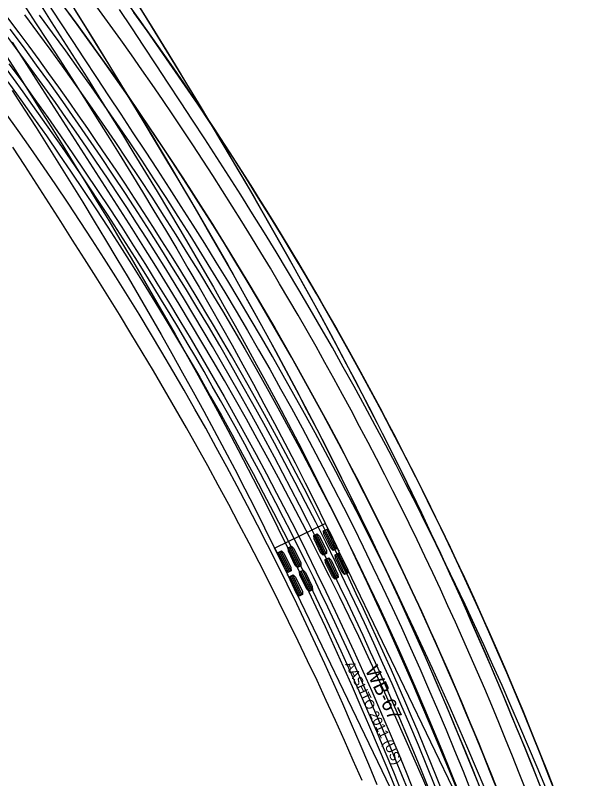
# Model space of a CAD drawing. Extents: x 916040 to 917457, y 328936 to 330267.
# Drawn here: x 916742.6 to 916826.9, y 329306.5 to 329421.5 of the extents above; entities that cross this region are included whole.
import ezdxf

# ---------------------------------------------------------------- set-up
doc = ezdxf.new("R2010")
doc.units = 0
for name, color, linetype in [('EB_RightontoSaco_WB67_v2', 7, 'Continuous'), ('NB_LeftontoRoute25_WB67', 7, 'Continuous'), ('NB_RightontoRoute25_WB67', 7, 'Continuous'), ('NB_ThruontoManchester_WB67', 7, 'Continuous'), ('SB_LeftontoRoute25_WB67', 7, 'Continuous'), ('SB_ThruontonSacoRd_WB67', 7, 'Continuous'), ('WB_LeftontoSaco_WB67', 7, 'Continuous')]:
    doc.layers.add(name, color=color, linetype=linetype)

msp = doc.modelspace()

# ---------------------------------------------------------------- linework, layer by layer
at = {"layer": 'EB_RightontoSaco_WB67_v2'}
for points in [[(916746.23, 329423.34), (916748.03, 329420.53), (916749.83, 329417.72), (916751.62, 329414.9), (916753.41, 329412.08), (916755.19, 329409.25), (916756.96, 329406.41), (916758.72, 329403.57), (916760.47, 329400.72), (916762.21, 329397.87), (916763.94, 329395), (916765.66, 329392.14), (916767.37, 329389.26), (916769.06, 329386.37), (916770.74, 329383.48), (916772.41, 329380.58), (916774.06, 329377.67), (916775.7, 329374.76), (916777.32, 329371.83), (916778.93, 329368.9), (916780.53, 329365.96), (916782.1, 329363.01), (916783.67, 329360.05), (916785.21, 329357.08), (916786.74, 329354.1), (916788.25, 329351.12), (916789.75, 329348.12), (916791.22, 329345.12), (916792.68, 329342.11), (916794.12, 329339.09), (916795.55, 329336.05), (916796.96, 329333.01), (916798.35, 329329.96), (916799.72, 329326.9), (916801.08, 329323.84), (916802.42, 329320.77), (916803.75, 329317.69), (916805.06, 329314.6), (916806.35, 329311.51), (916807.63, 329308.41), (916808.9, 329305.31)], [(916746.2, 329421.54), (916748.18, 329418.86), (916750.14, 329416.17), (916752.09, 329413.46), (916754.02, 329410.73), (916755.94, 329407.99), (916757.83, 329405.23), (916759.72, 329402.46), (916761.58, 329399.68), (916763.43, 329396.88), (916765.25, 329394.07), (916767.07, 329391.24), (916768.86, 329388.41), (916770.63, 329385.56), (916772.39, 329382.7), (916774.13, 329379.82), (916775.85, 329376.94), (916777.54, 329374.04), (916779.23, 329371.13), (916780.89, 329368.21), (916782.53, 329365.28), (916784.15, 329362.34), (916785.76, 329359.39), (916787.34, 329356.43), (916788.91, 329353.45), (916790.45, 329350.47), (916791.98, 329347.47), (916793.48, 329344.47), (916794.97, 329341.46), (916796.43, 329338.43), (916797.88, 329335.4), (916799.31, 329332.35), (916800.71, 329329.3), (916802.1, 329326.24), (916803.46, 329323.17), (916804.81, 329320.09), (916806.13, 329317), (916807.44, 329313.9), (916808.72, 329310.8), (916809.98, 329307.68), (916811.23, 329304.56)], [(916740.88, 329415.95), (916742.67, 329413.15), (916744.45, 329410.35), (916746.22, 329407.54), (916747.99, 329404.73), (916749.74, 329401.92), (916751.49, 329399.1), (916753.22, 329396.28), (916754.95, 329393.45), (916756.66, 329390.62), (916758.36, 329387.78), (916760.05, 329384.94), (916761.72, 329382.09), (916763.38, 329379.23), (916765.03, 329376.36), (916766.66, 329373.49), (916768.28, 329370.61), (916769.88, 329367.72), (916771.47, 329364.83), (916773.04, 329361.93), (916774.6, 329359.02), (916776.14, 329356.1), (916777.66, 329353.17), (916779.17, 329350.24), (916780.66, 329347.3), (916782.13, 329344.35), (916783.59, 329341.39), (916785.02, 329338.42), (916786.44, 329335.44), (916787.85, 329332.46), (916789.24, 329329.46), (916790.61, 329326.45), (916791.96, 329323.44), (916793.3, 329320.42), (916794.62, 329317.38), (916795.93, 329314.34), (916797.22, 329311.3), (916798.51, 329308.24), (916799.77, 329305.18)], [(916741.66, 329414.23), (916743.62, 329411.53), (916745.57, 329408.83), (916747.49, 329406.11), (916749.39, 329403.38), (916751.28, 329400.65), (916753.14, 329397.9), (916754.99, 329395.14), (916756.82, 329392.37), (916758.62, 329389.6), (916760.41, 329386.8), (916762.18, 329384), (916763.93, 329381.19), (916765.66, 329378.37), (916767.38, 329375.53), (916769.07, 329372.69), (916770.74, 329369.83), (916772.4, 329366.97), (916774.03, 329364.09), (916775.65, 329361.2), (916777.25, 329358.3), (916778.83, 329355.39), (916780.39, 329352.48), (916781.93, 329349.55), (916783.45, 329346.61), (916784.95, 329343.66), (916786.43, 329340.7), (916787.89, 329337.73), (916789.33, 329334.75), (916790.75, 329331.77), (916792.16, 329328.77), (916793.54, 329325.77), (916794.9, 329322.75), (916796.24, 329319.73), (916797.57, 329316.69), (916798.87, 329313.65), (916800.15, 329310.6), (916801.41, 329307.55), (916802.65, 329304.48)]]:
    msp.add_lwpolyline(points, dxfattribs=at)
msp.add_arc((916337.91, 329118.02), 504.75, 18.7715, 37.1675, dxfattribs=at)
at = {"layer": 'NB_LeftontoRoute25_WB67'}
for points in [[(916760.52, 329424.03), (916762.27, 329421.19), (916764.02, 329418.34), (916765.77, 329415.49), (916767.51, 329412.63), (916769.24, 329409.77), (916770.97, 329406.9), (916772.69, 329404.03), (916774.39, 329401.15), (916776.09, 329398.26), (916777.78, 329395.37), (916779.46, 329392.47), (916781.13, 329389.57), (916782.78, 329386.65), (916784.42, 329383.73), (916786.05, 329380.81), (916787.66, 329377.87), (916789.27, 329374.93), (916790.85, 329371.98), (916792.42, 329369.02), (916793.98, 329366.05), (916795.52, 329363.08), (916797.05, 329360.09), (916798.56, 329357.1), (916800.05, 329354.1), (916801.53, 329351.1), (916802.99, 329348.08), (916804.43, 329345.06), (916805.86, 329342.03), (916807.26, 329338.99), (916808.65, 329335.95), (916810.03, 329332.9), (916811.38, 329329.84), (916812.72, 329326.77), (916814.05, 329323.7), (916815.36, 329320.62), (916816.66, 329317.53), (916817.94, 329314.44), (916819.21, 329311.35), (916820.47, 329308.25), (916821.71, 329305.15)], [(916749.78, 329423.01), (916751.76, 329420.32), (916753.72, 329417.62), (916755.65, 329414.92), (916757.57, 329412.2), (916759.48, 329409.47), (916761.36, 329406.72), (916763.22, 329403.97), (916765.06, 329401.21), (916766.89, 329398.44), (916768.7, 329395.65), (916770.49, 329392.86), (916772.26, 329390.05), (916774.01, 329387.24), (916775.74, 329384.41), (916777.46, 329381.57), (916779.15, 329378.72), (916780.83, 329375.86), (916782.49, 329372.99), (916784.13, 329370.11), (916785.75, 329367.22), (916787.35, 329364.32), (916788.93, 329361.41), (916790.5, 329358.49), (916792.04, 329355.55), (916793.57, 329352.61), (916795.08, 329349.66), (916796.57, 329346.7), (916798.04, 329343.73), (916799.48, 329340.75), (916800.92, 329337.76), (916802.33, 329334.76), (916803.72, 329331.76), (916805.09, 329328.74), (916806.44, 329325.71), (916807.78, 329322.68), (916809.09, 329319.64), (916810.38, 329316.59), (916811.66, 329313.53), (916812.91, 329310.46), (916814.15, 329307.39), (916815.36, 329304.3)], [(916751.53, 329422.4), (916753.29, 329419.57), (916755.03, 329416.73), (916756.78, 329413.89), (916758.51, 329411.06), (916760.24, 329408.21), (916761.97, 329405.37), (916763.68, 329402.52), (916765.38, 329399.67), (916767.08, 329396.82), (916768.76, 329393.96), (916770.43, 329391.1), (916772.1, 329388.23), (916773.74, 329385.35), (916775.38, 329382.47), (916777, 329379.58), (916778.61, 329376.69), (916780.21, 329373.79), (916781.79, 329370.88), (916783.36, 329367.97), (916784.91, 329365.05), (916786.45, 329362.12), (916787.97, 329359.18), (916789.47, 329356.24), (916790.96, 329353.29), (916792.43, 329350.33), (916793.89, 329347.37), (916795.33, 329344.4), (916796.75, 329341.41), (916798.16, 329338.43), (916799.54, 329335.44), (916800.91, 329332.44), (916802.27, 329329.43), (916803.61, 329326.41), (916804.93, 329323.38), (916806.24, 329320.35), (916807.53, 329317.31), (916808.81, 329314.26), (916810.08, 329311.2), (916811.34, 329308.14), (916812.58, 329305.07)], [(916760.21, 329422.3), (916762.15, 329419.58), (916764.09, 329416.84), (916766, 329414.09), (916767.9, 329411.33), (916769.78, 329408.55), (916771.65, 329405.76), (916773.49, 329402.95), (916775.32, 329400.13), (916777.14, 329397.3), (916778.93, 329394.46), (916780.71, 329391.61), (916782.47, 329388.74), (916784.21, 329385.86), (916785.93, 329382.97), (916787.63, 329380.07), (916789.31, 329377.16), (916790.98, 329374.24), (916792.63, 329371.31), (916794.25, 329368.36), (916795.86, 329365.41), (916797.45, 329362.44), (916799.02, 329359.46), (916800.57, 329356.48), (916802.1, 329353.48), (916803.62, 329350.48), (916805.11, 329347.46), (916806.58, 329344.44), (916808.04, 329341.4), (916809.47, 329338.36), (916810.89, 329335.3), (916812.28, 329332.24), (916813.66, 329329.17), (916815.01, 329326.09), (916816.35, 329323), (916817.66, 329319.9), (916818.96, 329316.8), (916820.23, 329313.68), (916821.49, 329310.56), (916822.72, 329307.43), (916823.94, 329304.29)]]:
    msp.add_lwpolyline(points, dxfattribs=at)
msp.add_arc((916337.91, 329118.02), 516.5, 18.7715, 38.2197, dxfattribs=at)
at = {"layer": 'NB_RightontoRoute25_WB67'}
for points in [[(916813.31, 329304.99), (916812.03, 329308.03), (916810.73, 329311.08), (916809.41, 329314.11), (916808.08, 329317.14), (916806.74, 329320.15), (916805.37, 329323.17), (916803.99, 329326.17), (916802.6, 329329.16), (916801.19, 329332.15), (916799.76, 329335.13), (916798.31, 329338.1), (916796.85, 329341.06), (916795.37, 329344.01), (916793.88, 329346.95), (916792.36, 329349.89), (916790.83, 329352.81), (916789.29, 329355.73), (916787.72, 329358.63), (916786.14, 329361.53), (916784.54, 329364.41), (916782.92, 329367.29), (916781.29, 329370.15), (916779.64, 329373.01), (916777.97, 329375.85), (916776.28, 329378.69), (916774.57, 329381.51), (916772.85, 329384.32), (916771.11, 329387.13), (916769.36, 329389.92), (916767.58, 329392.71), (916765.79, 329395.5), (916763.99, 329398.28), (916762.18, 329401.06), (916760.36, 329403.84), (916758.53, 329406.61), (916756.7, 329409.39), (916754.86, 329412.17), (916753.03, 329414.95), (916751.2, 329417.73), (916749.37, 329420.52), (916747.55, 329423.32)], [(916815.41, 329304.18), (916814.19, 329307.27), (916812.96, 329310.35), (916811.7, 329313.42), (916810.43, 329316.48), (916809.13, 329319.53), (916807.82, 329322.58), (916806.49, 329325.62), (916805.13, 329328.64), (916803.76, 329331.66), (916802.37, 329334.67), (916800.96, 329337.67), (916799.53, 329340.66), (916798.08, 329343.64), (916796.61, 329346.61), (916795.12, 329349.57), (916793.62, 329352.52), (916792.09, 329355.46), (916790.55, 329358.4), (916788.98, 329361.32), (916787.4, 329364.23), (916785.8, 329367.13), (916784.18, 329370.02), (916782.54, 329372.9), (916780.88, 329375.77), (916779.21, 329378.63), (916777.51, 329381.48), (916775.8, 329384.31), (916774.07, 329387.14), (916772.32, 329389.95), (916770.55, 329392.76), (916768.77, 329395.55), (916766.96, 329398.33), (916765.14, 329401.1), (916763.3, 329403.85), (916761.45, 329406.6), (916759.57, 329409.33), (916757.68, 329412.05), (916755.77, 329414.76), (916753.84, 329417.45), (916751.9, 329420.13), (916749.94, 329422.81)], [(916822.44, 329305.17), (916821.15, 329308.27), (916819.85, 329311.35), (916818.54, 329314.43), (916817.2, 329317.51), (916815.85, 329320.58), (916814.49, 329323.64), (916813.11, 329326.69), (916811.71, 329329.73), (916810.3, 329332.77), (916808.86, 329335.8), (916807.41, 329338.82), (916805.95, 329341.84), (916804.46, 329344.84), (916802.96, 329347.84), (916801.44, 329350.82), (916799.91, 329353.8), (916798.35, 329356.77), (916796.78, 329359.73), (916795.19, 329362.68), (916793.59, 329365.62), (916791.96, 329368.55), (916790.32, 329371.47), (916788.66, 329374.39), (916786.98, 329377.29), (916785.28, 329380.18), (916783.57, 329383.06), (916781.84, 329385.92), (916780.09, 329388.78), (916778.32, 329391.63), (916776.54, 329394.46), (916774.75, 329397.29), (916772.94, 329400.1), (916771.12, 329402.91), (916769.29, 329405.71), (916767.46, 329408.5), (916765.63, 329411.29), (916763.79, 329414.07), (916761.96, 329416.85), (916760.13, 329419.63), (916758.3, 329422.4)], [(916824.13, 329303.8), (916822.92, 329306.93), (916821.69, 329310.06), (916820.44, 329313.18), (916819.17, 329316.29), (916817.88, 329319.39), (916816.57, 329322.49), (916815.24, 329325.58), (916813.88, 329328.66), (916812.51, 329331.73), (916811.12, 329334.79), (916809.71, 329337.85), (916808.28, 329340.89), (916806.83, 329343.93), (916805.36, 329346.95), (916803.87, 329349.97), (916802.36, 329352.98), (916800.83, 329355.97), (916799.28, 329358.96), (916797.72, 329361.94), (916796.13, 329364.91), (916794.52, 329367.86), (916792.9, 329370.81), (916791.26, 329373.75), (916789.59, 329376.67), (916787.91, 329379.59), (916786.21, 329382.49), (916784.49, 329385.38), (916782.75, 329388.27), (916781, 329391.14), (916779.22, 329394), (916777.43, 329396.84), (916775.62, 329399.68), (916773.79, 329402.5), (916771.94, 329405.32), (916770.07, 329408.12), (916768.19, 329410.9), (916766.28, 329413.68), (916764.36, 329416.44), (916762.43, 329419.19), (916760.47, 329421.93)]]:
    msp.add_lwpolyline(points, dxfattribs=at)
msp.add_arc((916337.91, 329118.02), 516.5, 18.7715, 38.2197, dxfattribs=at)
at = {"layer": 'NB_ThruontoManchester_WB67'}
for points in [[(916750.67, 329423.83), (916752.43, 329420.99), (916754.18, 329418.16), (916755.92, 329415.32), (916757.66, 329412.48), (916759.39, 329409.64), (916761.12, 329406.8), (916762.83, 329403.96), (916764.54, 329401.11), (916766.24, 329398.25), (916767.93, 329395.4), (916769.61, 329392.53), (916771.27, 329389.67), (916772.93, 329386.79), (916774.57, 329383.92), (916776.2, 329381.03), (916777.82, 329378.14), (916779.42, 329375.24), (916781.01, 329372.34), (916782.58, 329369.43), (916784.14, 329366.51), (916785.68, 329363.59), (916787.21, 329360.66), (916788.73, 329357.72), (916790.22, 329354.77), (916791.7, 329351.82), (916793.17, 329348.85), (916794.62, 329345.88), (916796.05, 329342.91), (916797.46, 329339.93), (916798.85, 329336.94), (916800.23, 329333.94), (916801.59, 329330.94), (916802.94, 329327.92), (916804.27, 329324.9), (916805.59, 329321.87), (916806.89, 329318.83), (916808.18, 329315.78), (916809.45, 329312.73), (916810.71, 329309.67), (916811.96, 329306.6), (916813.2, 329303.53)], [(916759.23, 329423.66), (916761.18, 329420.94), (916763.12, 329418.21), (916765.05, 329415.47), (916766.95, 329412.71), (916768.84, 329409.94), (916770.72, 329407.15), (916772.57, 329404.36), (916774.41, 329401.54), (916776.23, 329398.72), (916778.04, 329395.88), (916779.82, 329393.04), (916781.59, 329390.18), (916783.34, 329387.3), (916785.07, 329384.42), (916786.78, 329381.53), (916788.47, 329378.62), (916790.15, 329375.7), (916791.8, 329372.77), (916793.44, 329369.83), (916795.06, 329366.88), (916796.66, 329363.92), (916798.24, 329360.95), (916799.8, 329357.97), (916801.34, 329354.98), (916802.86, 329351.98), (916804.37, 329348.97), (916805.85, 329345.95), (916807.31, 329342.92), (916808.76, 329339.88), (916810.18, 329336.83), (916811.59, 329333.77), (916812.97, 329330.71), (916814.34, 329327.63), (916815.68, 329324.55), (916817.01, 329321.45), (916818.31, 329318.35), (916819.6, 329315.24), (916820.86, 329312.12), (916822.11, 329309), (916823.33, 329305.86)], [(916750.77, 329421.67), (916752.74, 329418.98), (916754.69, 329416.27), (916756.62, 329413.56), (916758.53, 329410.83), (916760.42, 329408.1), (916762.29, 329405.35), (916764.14, 329402.59), (916765.98, 329399.83), (916767.8, 329397.05), (916769.59, 329394.26), (916771.37, 329391.46), (916773.13, 329388.65), (916774.88, 329385.82), (916776.6, 329382.99), (916778.31, 329380.15), (916779.99, 329377.29), (916781.66, 329374.43), (916783.31, 329371.55), (916784.94, 329368.67), (916786.55, 329365.77), (916788.14, 329362.86), (916789.72, 329359.95), (916791.27, 329357.02), (916792.81, 329354.08), (916794.33, 329351.14), (916795.82, 329348.18), (916797.3, 329345.22), (916798.76, 329342.24), (916800.2, 329339.26), (916801.62, 329336.26), (916803.02, 329333.26), (916804.41, 329330.25), (916805.77, 329327.23), (916807.11, 329324.2), (916808.44, 329321.16), (916809.74, 329318.11), (916811.02, 329315.06), (916812.29, 329312), (916813.53, 329308.93), (916814.76, 329305.85)], [(916761.41, 329422.62), (916763.16, 329419.77), (916764.91, 329416.92), (916766.65, 329414.06), (916768.39, 329411.2), (916770.12, 329408.34), (916771.84, 329405.47), (916773.55, 329402.59), (916775.25, 329399.71), (916776.95, 329396.82), (916778.63, 329393.93), (916780.3, 329391.02), (916781.96, 329388.11), (916783.61, 329385.2), (916785.24, 329382.27), (916786.86, 329379.34), (916788.47, 329376.4), (916790.07, 329373.46), (916791.64, 329370.5), (916793.21, 329367.54), (916794.76, 329364.57), (916796.29, 329361.59), (916797.81, 329358.6), (916799.31, 329355.61), (916800.8, 329352.6), (916802.27, 329349.59), (916803.72, 329346.57), (916805.15, 329343.54), (916806.57, 329340.51), (916807.96, 329337.47), (916809.34, 329334.42), (916810.71, 329331.37), (916812.06, 329328.31), (916813.39, 329325.24), (916814.71, 329322.16), (916816.01, 329319.08), (916817.3, 329315.99), (916818.58, 329312.9), (916819.84, 329309.8), (916821.09, 329306.7), (916822.33, 329303.59)]]:
    msp.add_lwpolyline(points, dxfattribs=at)
msp.add_arc((916337.91, 329118.02), 516.5, 18.7715, 38.2197, dxfattribs=at)
at = {"layer": 'SB_LeftontoRoute25_WB67'}
msp.add_arc((916337.91, 329118.02), 500, 18.7715, 37.1675, dxfattribs=at)
at = {"layer": 'SB_ThruontonSacoRd_WB67'}
for points in [[(916805.8, 329305.36), (916804.54, 329308.47), (916803.26, 329311.58), (916801.96, 329314.68), (916800.64, 329317.77), (916799.3, 329320.85), (916797.93, 329323.92), (916796.55, 329326.99), (916795.14, 329330.04), (916793.72, 329333.09), (916792.27, 329336.12), (916790.81, 329339.15), (916789.32, 329342.17), (916787.82, 329345.18), (916786.29, 329348.17), (916784.74, 329351.16), (916783.18, 329354.14), (916781.59, 329357.1), (916779.99, 329360.06), (916778.36, 329363.01), (916776.72, 329365.94), (916775.05, 329368.86), (916773.37, 329371.78), (916771.66, 329374.68), (916769.94, 329377.57), (916768.2, 329380.44), (916766.44, 329383.31), (916764.66, 329386.17), (916762.86, 329389.01), (916761.04, 329391.84), (916759.2, 329394.66), (916757.35, 329397.46), (916755.47, 329400.26), (916753.58, 329403.04), (916751.67, 329405.8), (916749.74, 329408.56), (916747.79, 329411.3), (916745.82, 329414.03), (916743.84, 329416.75), (916741.83, 329419.45)], [(916805.23, 329303.51), (916803.92, 329306.59), (916802.59, 329309.66), (916801.25, 329312.73), (916799.89, 329315.79), (916798.51, 329318.84), (916797.12, 329321.89), (916795.71, 329324.92), (916794.28, 329327.95), (916792.83, 329330.98), (916791.37, 329333.99), (916789.89, 329336.99), (916788.39, 329339.99), (916786.87, 329342.97), (916785.34, 329345.95), (916783.79, 329348.92), (916782.21, 329351.87), (916780.63, 329354.82), (916779.02, 329357.76), (916777.39, 329360.69), (916775.75, 329363.61), (916774.08, 329366.51), (916772.4, 329369.41), (916770.7, 329372.3), (916768.99, 329375.17), (916767.25, 329378.04), (916765.51, 329380.9), (916763.74, 329383.75), (916761.97, 329386.58), (916760.19, 329389.42), (916758.4, 329392.24), (916756.6, 329395.06), (916754.8, 329397.87), (916752.99, 329400.68), (916751.18, 329403.48), (916749.38, 329406.28), (916747.57, 329409.08), (916745.77, 329411.88), (916743.97, 329414.68), (916742.18, 329417.48)], [(916797.07, 329305.62), (916795.8, 329308.69), (916794.52, 329311.74), (916793.21, 329314.79), (916791.89, 329317.83), (916790.54, 329320.85), (916789.18, 329323.87), (916787.8, 329326.88), (916786.39, 329329.88), (916784.97, 329332.87), (916783.52, 329335.85), (916782.06, 329338.82), (916780.57, 329341.78), (916779.07, 329344.73), (916777.55, 329347.67), (916776, 329350.6), (916774.44, 329353.52), (916772.86, 329356.43), (916771.26, 329359.33), (916769.64, 329362.22), (916768, 329365.09), (916766.34, 329367.96), (916764.66, 329370.81), (916762.96, 329373.65), (916761.25, 329376.49), (916759.51, 329379.31), (916757.76, 329382.11), (916755.99, 329384.91), (916754.2, 329387.7), (916752.39, 329390.47), (916750.56, 329393.23), (916748.71, 329395.98), (916746.85, 329398.71), (916744.97, 329401.44), (916743.06, 329404.15), (916741.15, 329406.85)], [(916794.8, 329306.27), (916793.47, 329309.3), (916792.13, 329312.32), (916790.77, 329315.33), (916789.4, 329318.33), (916788.01, 329321.32), (916786.6, 329324.31), (916785.18, 329327.29), (916783.73, 329330.25), (916782.28, 329333.21), (916780.8, 329336.16), (916779.31, 329339.1), (916777.8, 329342.03), (916776.27, 329344.95), (916774.72, 329347.87), (916773.15, 329350.77), (916771.57, 329353.66), (916769.97, 329356.54), (916768.35, 329359.41), (916766.72, 329362.27), (916765.06, 329365.12), (916763.39, 329367.96), (916761.7, 329370.8), (916759.99, 329373.62), (916758.27, 329376.44), (916756.53, 329379.26), (916754.77, 329382.07), (916753, 329384.87), (916751.22, 329387.68), (916749.44, 329390.48), (916747.64, 329393.28), (916745.84, 329396.08), (916744.04, 329398.88), (916742.23, 329401.68)]]:
    msp.add_lwpolyline(points, dxfattribs=at)
msp.add_arc((916337.91, 329118.02), 500, 18.7715, 37.1675, dxfattribs=at)
at = {"layer": 'WB_LeftontoSaco_WB67'}
for p, q in [((916789.3, 329344.98), (916781.65, 329341.29)), ((916812.3, 329297.22), (916789.3, 329344.98)), ((916790.49, 329340.94), (916789.05, 329343.91)), ((916790.69, 329341.04), (916789.26, 329344.01)), ((916790.9, 329341.14), (916789.47, 329344.11)), ((916789, 329340.22), (916787.57, 329343.2)), ((916789.21, 329340.32), (916787.77, 329343.3)), ((916789.41, 329340.42), (916787.98, 329343.39)), ((916781.65, 329341.29), (916804.64, 329293.54)), ((916785.14, 329338.36), (916783.71, 329341.34)), ((916785.35, 329338.46), (916783.91, 329341.44)), ((916785.55, 329338.56), (916784.12, 329341.54)), ((916783.65, 329337.65), (916782.22, 329340.62)), ((916783.86, 329337.75), (916782.43, 329340.72)), ((916784.07, 329337.85), (916782.63, 329340.82)), ((916792.22, 329337.33), (916790.79, 329340.31)), ((916792.43, 329337.43), (916791, 329340.41)), ((916792.63, 329337.53), (916791.2, 329340.51)), ((916790.73, 329336.62), (916789.3, 329339.59)), ((916790.94, 329336.72), (916789.51, 329339.69)), ((916791.15, 329336.82), (916789.72, 329339.79)), ((916786.87, 329334.76), (916785.44, 329337.73)), ((916787.08, 329334.86), (916785.65, 329337.83)), ((916787.29, 329334.96), (916785.86, 329337.93)), ((916785.39, 329334.04), (916783.96, 329337.02)), ((916785.59, 329334.14), (916784.16, 329337.12)), ((916785.8, 329334.24), (916784.37, 329337.22))]:
    msp.add_line(p, q, dxfattribs=at)
for points in [[(916743.84, 329423.2), (916745.67, 329420.4), (916747.49, 329417.6), (916749.3, 329414.79), (916751.1, 329411.98), (916752.9, 329409.15), (916754.69, 329406.33), (916756.47, 329403.49), (916758.23, 329400.65), (916759.99, 329397.81), (916761.74, 329394.95), (916763.47, 329392.09), (916765.19, 329389.22), (916766.9, 329386.34), (916768.59, 329383.45), (916770.27, 329380.56), (916771.94, 329377.65), (916773.59, 329374.74), (916775.22, 329371.82), (916776.84, 329368.89), (916778.44, 329365.95), (916780.03, 329363.01), (916781.6, 329360.05), (916783.16, 329357.08), (916784.7, 329354.11), (916786.22, 329351.13), (916787.72, 329348.14), (916789.21, 329345.14), (916790.67, 329342.13), (916791.26, 329340.92)], [(916743.98, 329421.59), (916745.97, 329418.91), (916747.95, 329416.21), (916749.91, 329413.5), (916751.85, 329410.77), (916753.77, 329408.03), (916755.68, 329405.27), (916757.57, 329402.5), (916759.45, 329399.72), (916761.3, 329396.92), (916763.14, 329394.11), (916764.96, 329391.29), (916766.76, 329388.45), (916768.54, 329385.61), (916770.31, 329382.75), (916772.05, 329379.87), (916773.78, 329376.99), (916775.49, 329374.1), (916777.18, 329371.19), (916778.84, 329368.27), (916780.49, 329365.34), (916782.12, 329362.4), (916783.74, 329359.45), (916785.33, 329356.49), (916786.9, 329353.52), (916788.45, 329350.53), (916789.98, 329347.54), (916791.49, 329344.54), (916792.99, 329341.52), (916794.46, 329338.5), (916795.91, 329335.47), (916797.34, 329332.42), (916798.76, 329329.37), (916800.15, 329326.31), (916801.52, 329323.24), (916802.87, 329320.16), (916804.2, 329317.07), (916805.51, 329313.98), (916806.8, 329310.87), (916808.07, 329307.76), (916809.32, 329304.63)], [(916741.49, 329411.49), (916743.44, 329408.79), (916745.37, 329406.08), (916747.28, 329403.36), (916749.17, 329400.63), (916751.04, 329397.89), (916752.89, 329395.14), (916754.72, 329392.38), (916756.53, 329389.6), (916758.33, 329386.82), (916760.1, 329384.02), (916761.86, 329381.21), (916763.6, 329378.39), (916765.32, 329375.56), (916767.02, 329372.72), (916768.7, 329369.86), (916770.36, 329367), (916772, 329364.13), (916773.63, 329361.24), (916775.23, 329358.34), (916776.81, 329355.44), (916778.38, 329352.52), (916779.93, 329349.59), (916781.45, 329346.66), (916782.96, 329343.71), (916784.45, 329340.75), (916785.91, 329337.79), (916787.36, 329334.81), (916788.79, 329331.82), (916790.2, 329328.83), (916791.59, 329325.82), (916792.96, 329322.81), (916794.3, 329319.79), (916795.63, 329316.75), (916796.94, 329313.71), (916798.23, 329310.67), (916799.5, 329307.61), (916800.74, 329304.54)], [(916742.15, 329410.19), (916743.94, 329407.4), (916745.73, 329404.6), (916747.5, 329401.8), (916749.26, 329398.99), (916751.01, 329396.18), (916752.75, 329393.36), (916754.48, 329390.53), (916756.19, 329387.7), (916757.89, 329384.86), (916759.58, 329382.02), (916761.25, 329379.17), (916762.91, 329376.31), (916764.55, 329373.44), (916766.18, 329370.57), (916767.79, 329367.69), (916769.39, 329364.8), (916770.97, 329361.9), (916772.54, 329358.99), (916774.09, 329356.08), (916775.62, 329353.16), (916777.14, 329350.23), (916778.64, 329347.29), (916780.12, 329344.34), (916781.58, 329341.39), (916783.02, 329338.42), (916783.6, 329337.23)]]:
    msp.add_lwpolyline(points, dxfattribs=at)
for points in [[(916790.95, 329341.16), (916790.43, 329340.91), (916790.08, 329341.26), (916789.05, 329343.4), (916789, 329343.89), (916789.52, 329344.14), (916789.87, 329343.79), (916790.9, 329341.65)], [(916789.46, 329340.45), (916788.95, 329340.2), (916788.59, 329340.54), (916787.56, 329342.68), (916787.52, 329343.17), (916788.03, 329343.42), (916788.39, 329343.08), (916789.42, 329340.94)], [(916785.6, 329338.59), (916785.09, 329338.34), (916784.73, 329338.68), (916783.7, 329340.82), (916783.66, 329341.31), (916784.17, 329341.56), (916784.53, 329341.22), (916785.56, 329339.08)], [(916784.12, 329337.87), (916783.6, 329337.62), (916783.25, 329337.97), (916782.21, 329340.11), (916782.17, 329340.6), (916782.69, 329340.85), (916783.04, 329340.5), (916784.07, 329338.36)], [(916792.68, 329337.56), (916792.17, 329337.31), (916791.81, 329337.65), (916790.78, 329339.79), (916790.74, 329340.28), (916791.25, 329340.53), (916791.61, 329340.19), (916792.64, 329338.05)], [(916791.2, 329336.84), (916790.68, 329336.59), (916790.33, 329336.94), (916789.3, 329339.08), (916789.25, 329339.57), (916789.77, 329339.82), (916790.12, 329339.47), (916791.15, 329337.33)], [(916787.34, 329334.98), (916786.82, 329334.74), (916786.47, 329335.08), (916785.44, 329337.22), (916785.39, 329337.71), (916785.91, 329337.96), (916786.26, 329337.62), (916787.29, 329335.48)], [(916785.85, 329334.27), (916785.34, 329334.02), (916784.98, 329334.36), (916783.95, 329336.5), (916783.91, 329336.99), (916784.42, 329337.24), (916784.78, 329336.9), (916785.81, 329334.76)]]:
    msp.add_lwpolyline(points, close=True, dxfattribs=at)
for centre in [(916791.26, 329340.92), (916783.6, 329337.23)]:
    msp.add_circle(centre, 0.0417, dxfattribs=at)
msp.add_arc((916337.91, 329118.02), 503, 18.7715, 38.6853, dxfattribs=at)

# ---------------------------------------------------------------- texts
for s, height, p in [('AASHTO 2011 (US)', 1.4167, (916792.23, 329323.8)), ('WB-67', 2.125, (916795.19, 329322.95))]:
    msp.add_text(s, height=height, rotation=295.7114, dxfattribs=at).set_placement(p)

doc.saveas('drawing.dxf')
